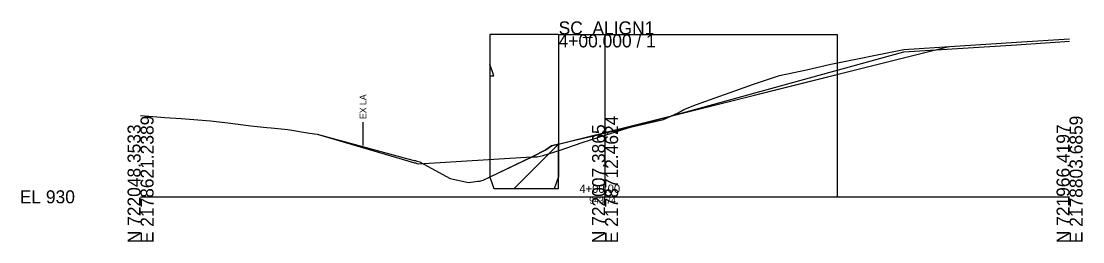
# Model space of a CAD drawing. Extents: x -2342 to 14913, y -10 to 5257.
# Drawn here: x 974.3 to 1202.8, y 2990.3 to 3037.8 of the extents above; entities that cross this region are included whole.
import ezdxf

# ---------------------------------------------------------------- set-up
doc = ezdxf.new("R2010")
doc.units = 0
for name, color, linetype in [('Default', 7, 'Continuous'), ('DR_P_Erosion_Control', 7, 'Continuous'), ('GK_Cells', 7, 'Continuous'), ('RW_X_Esmt_LA', 7, 'Continuous'), ('SC_Scratch1', 7, 'Continuous'), ('XS_P_Annotation', 7, 'Continuous'), ('XS_P_Finished_Grade', 7, 'Continuous'), ('XS_X_Ground_Line', 7, 'Continuous')]:
    doc.layers.add(name, color=color, linetype=linetype)

msp = doc.modelspace()

# ---------------------------------------------------------------- linework, layer by layer
at = {"layer": 'DR_P_Erosion_Control'}
msp.add_lwpolyline([(1076.04, 3001.76), (1080.4, 3001.76), (1090, 3011.36), (1090, 3011.36), (1088.46, 3010.99), (1087.26, 3010.13), (1084.33, 3008.59), (1075.16, 3004.26), (1076.04, 3001.76)], dxfattribs=at)
at = {"layer": 'GK_Cells'}
for p, q in [((1100, 3000), (1100, 3035)), ((1000, 3000), (1100, 3000)), ((1100, 3000), (1200, 3000))]:
    msp.add_line(p, q, dxfattribs=at)
at = {"layer": 'RW_X_Esmt_LA'}
msp.add_line((1047.89, 3011.06), (1047.89, 3016.06), dxfattribs=at)
at = {"layer": 'SC_Scratch1'}
for p, q in [((1090, 3035), (1075.16, 3035)), ((1075.16, 3035), (1075.16, 3004.26)), ((1090, 3035), (1090, 3004.26)), ((1150, 3035), (1150, 3000)), ((1088.46, 3010.99), (1150, 3026.38))]:
    msp.add_line(p, q, dxfattribs=at)
for points in [[(1090, 3035), (1100, 3035), (1150, 3035)], [(1000, 3017.53), (1001.76, 3017.38), (1005.25, 3017.06), (1008.77, 3016.85), (1015.08, 3016.37), (1018.81, 3015.92), (1023.74, 3015.29), (1027.16, 3014.93), (1028.14, 3014.89), (1031.71, 3014.47), (1036.36, 3013.74), (1038.03, 3013.48), (1057.52, 3007.74), (1057.57, 3007.73), (1058.94, 3007.35), (1059.2, 3007.29), (1059.49, 3007.21), (1059.8, 3007.11), (1084.14, 3008.61), (1085.31, 3008.6), (1085.35, 3008.61), (1086.67, 3008.92), (1090.35, 3010.03), (1095.04, 3011.7), (1103.4, 3014.38), (1104.94, 3014.87), (1164.33, 3031.24), (1188.54, 3032.78), (1200, 3033.53)], [(1080.4, 3001.76), (1089.08, 3001.76), (1090, 3004.26), (1090, 3011.36)], [(1089.08, 3001.76), (1090, 3001.76), (1090, 3004.26)]]:
    msp.add_lwpolyline(points, dxfattribs=at)
msp.add_lwpolyline([(1075.16, 3028.57), (1075.16, 3026.07), (1076.04, 3026.07)], close=True, dxfattribs=at)
at = {"layer": 'XS_P_Finished_Grade'}
msp.add_line((1090, 3011.36), (1174.02, 3032.36), dxfattribs=at)
at = {"layer": 'XS_X_Ground_Line'}
msp.add_lwpolyline([(1000, 3017.53), (1001.76, 3017.38), (1005.25, 3017.06), (1008.77, 3016.85), (1015.08, 3016.37), (1018.81, 3015.92), (1023.74, 3015.29), (1027.16, 3014.93), (1028.14, 3014.89), (1031.71, 3014.47), (1036.36, 3013.74), (1038.03, 3013.48), (1057.52, 3008.2), (1058.92, 3007.85), (1059.18, 3007.79), (1059.48, 3007.71), (1060.09, 3007.54), (1060.16, 3007.46), (1066.65, 3003.97), (1070.63, 3003.11), (1072.62, 3003.36), (1072.96, 3003.37), (1073.76, 3003.59), (1084.33, 3008.59), (1087.26, 3010.13), (1088.46, 3010.99), (1092.57, 3011.97), (1098.16, 3013.28), (1100.14, 3013.77), (1112.57, 3016.66), (1115.71, 3018.11), (1116.92, 3018.8), (1119.66, 3019.9), (1131.92, 3024.28), (1137.57, 3026.16), (1143.33, 3027.37), (1148.63, 3028.62), (1164.33, 3031.75), (1188.54, 3033.29), (1200, 3034.04)], dxfattribs=at)

# ---------------------------------------------------------------- texts
at = {"layer": 'Default'}
msp.add_text('-', height=0.0001, dxfattribs=at).set_placement((1000, 3000))
at = {"layer": 'GK_Cells'}
for s, p in [('SC_ALIGN1', (1090, 3035)), ('4+00.000 / 1', (1090, 3032.2)), ('EL 930', (974, 2998.6))]:
    msp.add_text(s, height=2.8, dxfattribs=at).set_placement(p)
for s, p in [('E 2178621.2389', (1002.8, 2990)), ('E 2178712.4624', (1102.8, 2990)), ('E 2178803.6859', (1202.8, 2990)), ('N 722048.3533', (1000, 2990)), ('N 722007.3865', (1100, 2990)), ('N 721966.4197', (1200, 2990))]:
    msp.add_text(s, height=2.8, rotation=90, dxfattribs=at).set_placement(p)
at = {"layer": 'RW_X_Esmt_LA'}
msp.add_text('EX LA', height=1.4, rotation=90, dxfattribs=at).set_placement((1048.59, 3016.76))
at = {"layer": 'SC_Scratch1'}
msp.add_text('X', height=0.0001, dxfattribs=at).set_placement((1100, 3013.74))
at = {"layer": 'XS_P_Annotation'}
for s, height, p in [('4+00.00', 1.8, (1094.47, 3000.84)), ('943.74', 1.4, (1096.59, 2998.54))]:
    msp.add_text(s, height=height, dxfattribs=at).set_placement(p)

doc.saveas('drawing.dxf')
